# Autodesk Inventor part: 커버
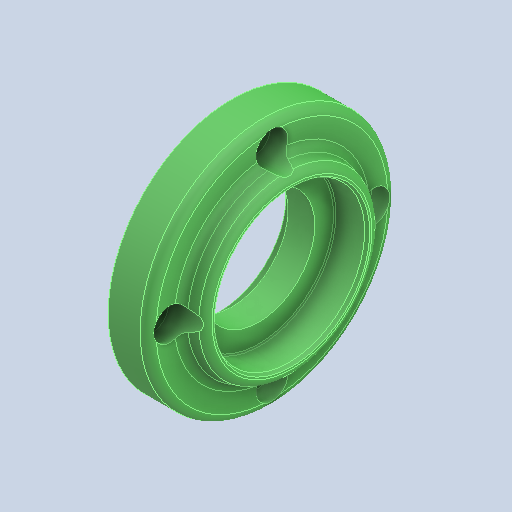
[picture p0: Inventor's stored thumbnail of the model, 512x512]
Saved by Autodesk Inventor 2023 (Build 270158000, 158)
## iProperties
Created: 2025-03
Part Number: 커버
Material: 알루미늄 6061
Document SubType Name: Modeling
Designer: user
Density: 2.71 g/cm^3
Appearance: 기본값
Author: jhkim
Sending System: Autodesk Inventor 2025
Preprocessor: ST-DEVELOPER v20
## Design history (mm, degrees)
feature "솔리드1"
node "솔리드2"
